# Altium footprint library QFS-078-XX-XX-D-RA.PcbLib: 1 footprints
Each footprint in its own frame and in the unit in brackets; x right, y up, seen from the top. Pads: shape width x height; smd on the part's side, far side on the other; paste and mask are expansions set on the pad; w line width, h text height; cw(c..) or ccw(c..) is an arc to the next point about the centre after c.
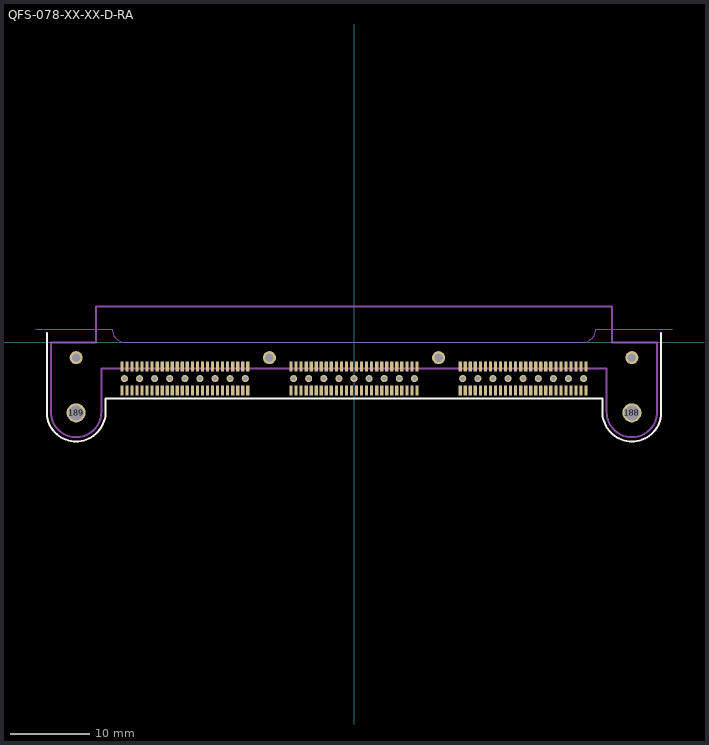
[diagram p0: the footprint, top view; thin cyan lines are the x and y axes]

## QFS-078-XX-XX-D-RA [mil]
pads (189):
  rect 16x50 smd mask+2: 1(1152.5,-241) 2(1152.5,-121) 3(1127.5,-241) 4(1127.5,-121) 5(1102.5,-241) 6(1102.5,-121) 7(1077.5,-241) 8(1077.5,-121) 9(1052.5,-241) 10(1052.5,-121) 11(1027.5,-241) 12(1027.5,-121) 13(1002.5,-241) 14(1002.5,-121) 15(977.5,-241) 16(977.5,-121) 17(952.5,-241) 18(952.5,-121) 19(927.5,-241) 20(927.5,-121) 21(902.5,-241) 22(902.5,-121) 23(877.5,-241) 24(877.5,-121) 25(852.5,-241) 26(852.5,-121) 27(827.5,-241) 28(827.5,-121) 29(802.5,-241) 30(802.5,-121) 31(777.5,-241) 32(777.5,-121) 33(752.5,-241) 34(752.5,-121) 35(727.5,-241) 36(727.5,-121) 37(702.5,-241) 38(702.5,-121) 39(677.5,-241) 40(677.5,-121) 41(652.5,-241) 42(652.5,-121) 43(627.5,-241) 44(627.5,-121) 45(602.5,-241) 46(602.5,-121) 47(577.5,-241) 48(577.5,-121) 49(552.5,-241) 50(552.5,-121) 51(527.5,-241) 52(527.5,-121) 53(312.5,-241) 54(312.5,-121) 55(287.5,-241) 56(287.5,-121) 57(262.5,-241) 58(262.5,-121) 59(237.5,-241) 60(237.5,-121) 61(212.5,-241) 62(212.5,-121) 63(187.5,-241) 64(187.5,-121) 65(162.5,-241) 66(162.5,-121) 67(137.5,-241) 68(137.5,-121) 69(112.5,-241) 70(112.5,-121) 71(87.5,-241) 72(87.5,-121) 73(62.5,-241) 74(62.5,-121) 75(37.5,-241) 76(37.5,-121) 77(12.5,-241) 78(12.5,-121) 79(-12.5,-241) 80(-12.5,-121) 81(-37.5,-241) 82(-37.5,-121) 83(-62.5,-241) 84(-62.5,-121) 85(-87.5,-241) 86(-87.5,-121) 87(-112.5,-241) 88(-112.5,-121) 89(-137.5,-241) 90(-137.5,-121) 91(-162.5,-241) 92(-162.5,-121) 93(-187.5,-241) 94(-187.5,-121) 95(-212.5,-241) 96(-212.5,-121) 97(-237.5,-241) 98(-237.5,-121) 99(-262.5,-241) 100(-262.5,-121) 101(-287.5,-241) 102(-287.5,-121) 103(-312.5,-241) 104(-312.5,-121) 105(-527.5,-241) 106(-527.5,-121) 107(-552.5,-241) 108(-552.5,-121) 109(-577.5,-241) 110(-577.5,-121) 111(-602.5,-241) 112(-602.5,-121) 113(-627.5,-241) 114(-627.5,-121) 115(-652.5,-241) 116(-652.5,-121) 117(-677.5,-241) 118(-677.5,-121) 119(-702.5,-241) 120(-702.5,-121) 121(-727.5,-241) 122(-727.5,-121) 123(-752.5,-241) 124(-752.5,-121) 125(-777.5,-241) 126(-777.5,-121) 127(-802.5,-241) 128(-802.5,-121) 129(-827.5,-241) 130(-827.5,-121) 131(-852.5,-241) 132(-852.5,-121) 133(-877.5,-241) 134(-877.5,-121) 135(-902.5,-241) 136(-902.5,-121) 137(-927.5,-241) 138(-927.5,-121) 139(-952.5,-241) 140(-952.5,-121) 141(-977.5,-241) 142(-977.5,-121) 143(-1002.5,-241) 144(-1002.5,-121) 145(-1027.5,-241) 146(-1027.5,-121) 147(-1052.5,-241) 148(-1052.5,-121) 149(-1077.5,-241) 150(-1077.5,-121) 151(-1102.5,-241) 152(-1102.5,-121) 153(-1127.5,-241) 154(-1127.5,-121) 155(-1152.5,-241) 156(-1152.5,-121)
  round 35 hole 21 mask+3: 157(1140,-181) 158(1065,-181) 159(990,-181) 160(915,-181) 161(840,-181) 162(765,-181) 163(690,-181) 164(615,-181) 165(540,-181) 166(300,-181) 167(225,-181) 168(150,-181) 169(75,-181) 170(0,-181) 171(-75,-181) 172(-150,-181) 173(-225,-181) 174(-300,-181) 175(-540,-181) 176(-615,-181) 177(-690,-181) 178(-765,-181) 179(-840,-181) 180(-915,-181) 181(-990,-181) 182(-1065,-181) 183(-1140,-181)
  round 65 hole 42 mask+3: 184(1380,-77) 185(420,-77) 186(-420,-77) 187(-1380,-77)
  round 95 hole 75 mask+3: 188(1380,-351) 189(-1380,-351)
Top Overlay:
  lines w10: -1525,45 -1525,-367 ccw(c-1380,-346.62) -1235,-367 -1235,-281 1235,-281 1235,-367 ; 1235.02,-367.13 ccw(c1380,-347.01) 1525.02,-366.87 ; 1525,-367 1525,45
Mechanical 1:
  lines w10: -1505,-347 ccw(c-1380,-347) -1255,-347 -1255,-131 1255,-131 1255,-347 ccw(c1380,-347) 1505,-347 1505,-1 1280,-1 1280,177 -1280,177 -1280,-1 -1505,-1 -1505,-347
  text "J1" at -17.57,51 h30
Mechanical 16:
  lines w0.4: -1580,65 -1200,65 ; -1200,64.97 ccw(c-1137.47,62.57) -1137.47,0 ; -1137.5,0 1137.5,0 ; 1137.47,0 ccw(c1137.47,62.57) 1200,64.97 ; 1200,65 1580,65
